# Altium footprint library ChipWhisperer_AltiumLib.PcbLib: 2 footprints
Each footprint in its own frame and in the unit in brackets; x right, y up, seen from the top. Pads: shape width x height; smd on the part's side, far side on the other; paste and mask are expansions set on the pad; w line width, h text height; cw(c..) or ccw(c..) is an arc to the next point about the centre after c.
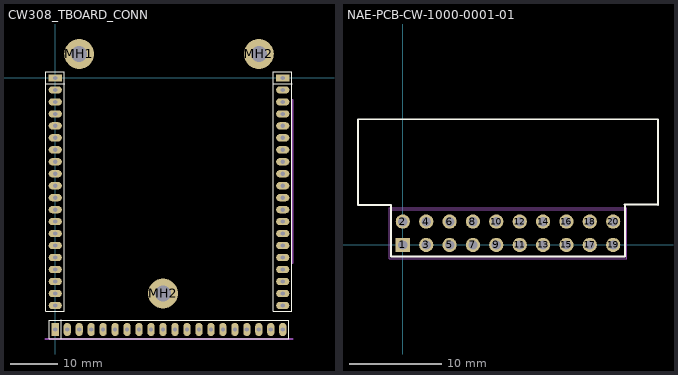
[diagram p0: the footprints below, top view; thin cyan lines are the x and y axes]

## CW308_TBOARD_CONN [mil]
pads (63):
  rect 110x60 hole 35: A1(0,0) C1(1900,0)
  oval 110x60 hole 35: A2(0,-100) A3(0,-200) A4(0,-300) A5(0,-400) A6(0,-500) A7(0,-600) A8(0,-700) A9(0,-800) A10(0,-900) A11(0,-1000) A12(0,-1100) A13(0,-1200) A14(0,-1300) A15(0,-1400) A16(0,-1500) A17(0,-1600) A18(0,-1700) A19(0,-1800) A20(0,-1900) C2(1900,-100) C3(1900,-200) C4(1900,-300) C5(1900,-400) C6(1900,-500) C7(1900,-600) C8(1900,-700) C9(1900,-800) C10(1900,-900) C11(1900,-1000) C12(1900,-1100) C13(1900,-1200) C14(1900,-1300) C15(1900,-1400) C16(1900,-1500) C17(1900,-1600) C18(1900,-1700) C19(1900,-1800) C20(1900,-1900)
  rect 60x110 hole 35: B1(0,-2100)
  oval 60x110 hole 35: B2(100,-2100) B3(200,-2100) B4(300,-2100) B5(400,-2100) B6(500,-2100) B7(600,-2100) B8(700,-2100) B9(800,-2100) B10(900,-2100) B11(1000,-2100) B12(1100,-2100) B13(1200,-2100) B14(1300,-2100) B15(1400,-2100) B16(1500,-2100) B17(1600,-2100) B18(1700,-2100) B19(1800,-2100) B20(1900,-2100)
  round 250 hole 134: MH1(200,200) MH2(900,-1800) MH2(1700,200)
Top Overlay:
  lines w10: -78.74,-50 78.74,-50 ; 50,-2178.74 50,-2021.26 ; 1821.26,-50 1978.74,-50 ; -78.74,-1950 -78.74,50 75,50 75,-1950 -78.74,-1950 ; -50,-2178.74 1950,-2178.74 1950,-2025 -50,-2025 -50,-2178.74 ; 1821.26,-1950 1821.26,50 1975,50 1975,-1950 1821.26,-1950
Mechanical 3:
  lines w15: -80,-2180 1980,-2180 ; 1980,-1545 1980,-185
3D body "pcb_connector_801-87-020-10-268101.stp": height 224.45, standoff 0, extent 1850,-1950 1950,50
3D body "pcb_connector_801-87-020-10-268101.stp": height 224.45, standoff 0, extent -50,-2150 1950,-2050
3D body "pcb_connector_801-87-020-10-268101.stp": height 224.45, standoff 0, extent -50,-1950 50,50

## NAE-PCB-CW-1000-0001-01 [mm] "High Temp Terminal Body, 2x10 Pins, R/A, 2.54mm Pitch, Male"
height 9.2
pads (20):
  rect 1.55x1.55 hole 1.02: 1(0,0)
  round 1.55 hole 1.02: 2(0,2.54) 3(2.54,0) 4(2.54,2.54) 5(5.08,0) 6(5.08,2.54) 7(7.62,0) 8(7.62,2.54) 9(10.16,0) 10(10.16,2.54) 11(12.7,0) 12(12.7,2.54) 13(15.24,0) 14(15.24,2.54) 15(17.78,0) 16(17.78,2.54) 17(20.32,0) 18(20.32,2.54) 19(22.86,0) 20(22.86,2.54)
Top Overlay:
  lines w0.2: -1.27,3.81 -1.27,-1.27 24.13,-1.27 24.13,3.81
  lines w0.203: -1.27,3.81 -1.27,4.37 -1.3,4.34 -4.875,4.34 -4.875,13.66 -4.875,13.66 27.735,13.66 ; 24.13,3.81 24.13,4.37 24.1,4.4 27.675,4.4 27.735,4.34 27.735,13.66 ; 27.735,13.66 27.735,13.66
Mechanical 13:
  lines w0.1: -1.27,-1.27 -1.27,3.81 24.13,3.81 24.13,-1.27 -1.27,-1.27
Mechanical 15:
  lines w0.05: -1.495,-1.495 -1.495,4.035 24.355,4.035 24.355,-1.495 -1.495,-1.495
3D body "75867_y04_asm.stp": height 9.27, standoff -3.07, extent -4.875,-0.31 27.735,13.66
